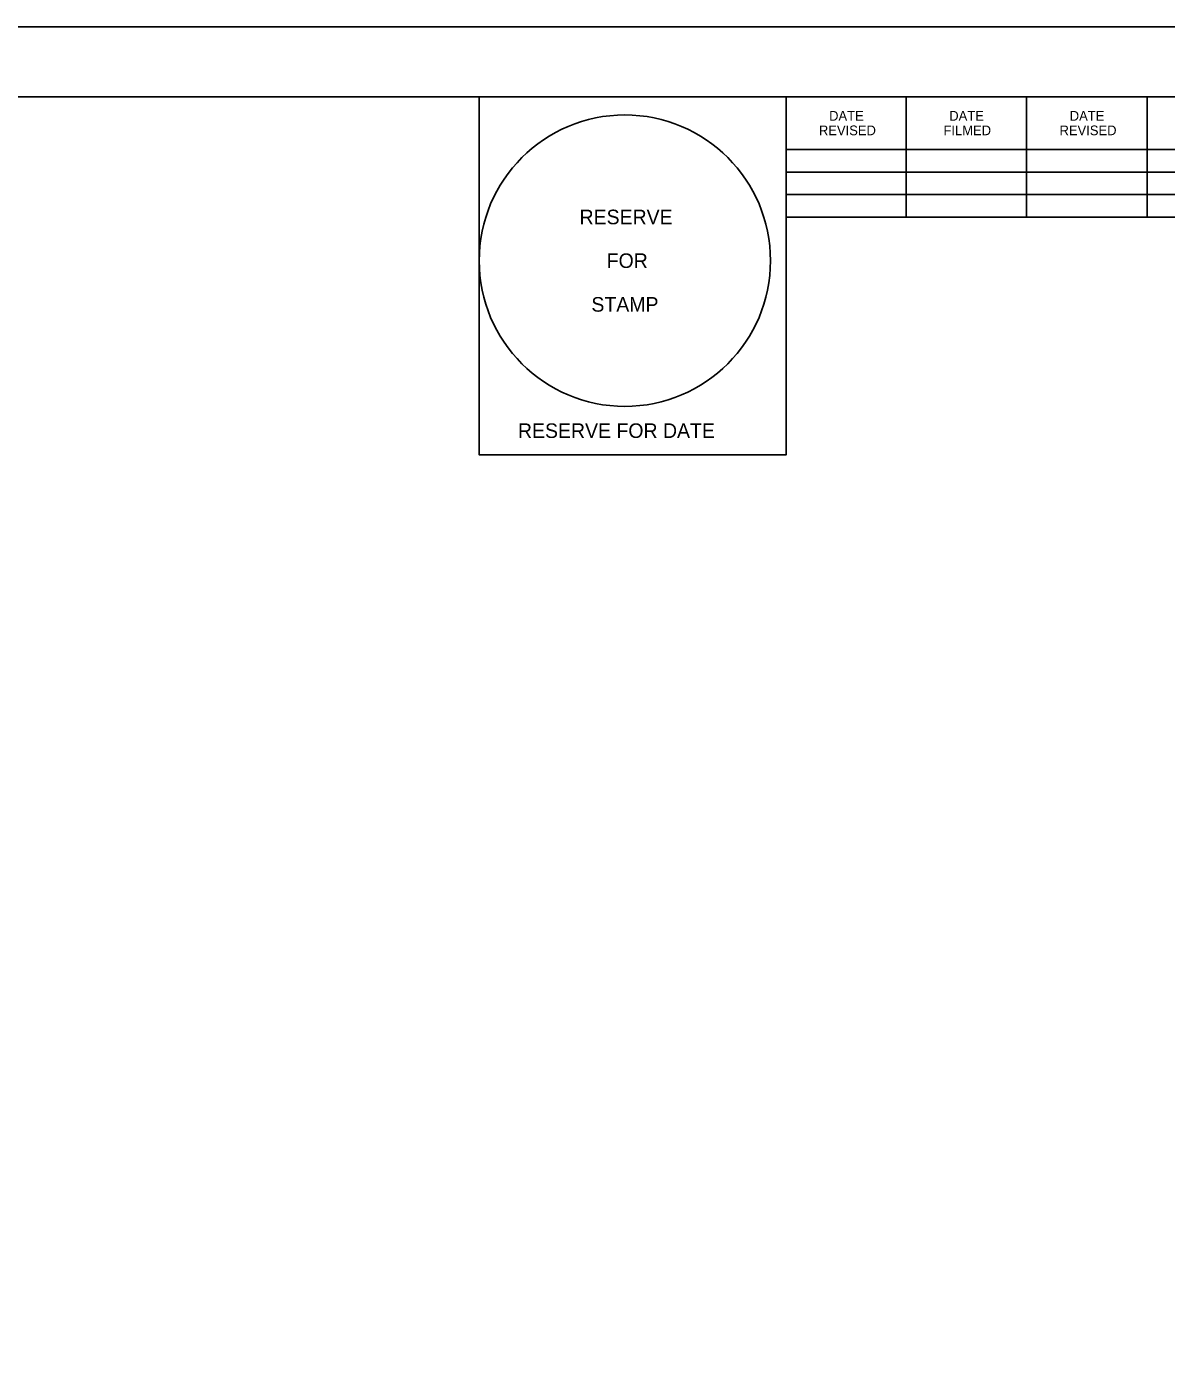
# Model space of a CAD drawing. Extents: x 0 to 762217, y -63 to 1662473.
# Drawn here: x 961 to 1430, y 550 to 1100 of the extents above; entities that cross this region are included whole.
import ezdxf

# ---------------------------------------------------------------- set-up
doc = ezdxf.new("R2010")
doc.units = 0
for name, color, linetype in [('G-ANNO-TEXT', 7, 'Continuous'), ('G-Border-Paper', 7, 'Continuous'), ('G-Border-Sheet', 7, 'Continuous'), ('G-No Plot-Border', 7, 'Continuous'), ('G-No Plot-Border-2', 7, 'Continuous'), ('G-No Plot-Stamp-2', 7, 'Continuous'), ('G-Table-Major', 7, 'Continuous'), ('G-Table-Minor', 7, 'Continuous')]:
    doc.layers.add(name, color=color, linetype=linetype)

msp = doc.modelspace()

# ---------------------------------------------------------------- linework, layer by layer
at = {"layer": 'G-Border-Paper'}
msp.add_lwpolyline([(1700.05, 1100), (0.05, 1100), (0.05, 0), (1700.05, 0)], close=True, dxfattribs=at)
at = {"layer": 'G-Border-Sheet'}
msp.add_line((75.85, 1071.16), (1671.21, 1071.16), dxfattribs=at)
at = {"layer": 'G-No Plot-Border'}
msp.add_lwpolyline([(75.85, 543.54), (75.85, 1071.16), (1273.86, 1071.16), (1273.86, 1021.61), (1472.11, 1021.61), (1472.11, 1006.11), (1543.71, 1006.11), (1543.71, 858.61), (1671.21, 858.61), (1671.21, 543.54)], close=True, dxfattribs=at)
at = {"layer": 'G-No Plot-Border-2'}
msp.add_lwpolyline([(75.85, 1071.16), (1147.43, 1071.16), (1147.43, 923.66), (1273.86, 923.66), (1273.86, 1021.61), (1472.11, 1021.61), (1472.11, 1006.11), (1671.21, 1006.11), (1671.21, 543.54), (75.85, 543.54)], close=True, dxfattribs=at)
at = {"layer": 'G-No Plot-Stamp-2'}
msp.add_circle((1207.43, 1003.66), 60, dxfattribs=at)
at = {"layer": 'G-Table-Major'}
for p, q in [((1273.86, 1021.61), (1273.86, 1071.16)), ((1372.86, 1021.68), (1372.86, 1071.16)), ((1273.86, 1049.46), (1472.11, 1049.46)), ((1671.21, 1021.61), (1273.86, 1021.61))]:
    msp.add_line(p, q, dxfattribs=at)
at = {"layer": 'G-Table-Minor'}
for p, q in [((1323.36, 1021.61), (1323.36, 1071.16)), ((1422.61, 1021.65), (1422.61, 1071.16)), ((1273.86, 1040.11), (1472.11, 1040.11)), ((1273.86, 1030.96), (1472.11, 1030.96))]:
    msp.add_line(p, q, dxfattribs=at)

# ---------------------------------------------------------------- texts
at = {"layer": 'G-ANNO-TEXT'}
for s, p in [('DATE', (1291.58, 1061.31)), ('DATE', (1341.08, 1061.31)), ('DATE', (1390.71, 1061.31)), ('REVISED', (1287.38, 1055.31)), ('FILMED', (1338.68, 1055.31)), ('REVISED', (1386.5, 1055.31))]:
    msp.add_text(s, height=4, dxfattribs=at).set_placement(p)
at = {"layer": 'G-No Plot-Stamp-2'}
for s, p in [('RESERVE', (1188.77, 1018.66)), ('FOR ', (1199.95, 1000.66)), ('STAMP', (1193.66, 982.66)), ('RESERVE FOR DATE', (1163.4, 930.66))]:
    msp.add_text(s, height=6, dxfattribs=at).set_placement(p)

doc.saveas('drawing.dxf')
